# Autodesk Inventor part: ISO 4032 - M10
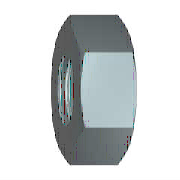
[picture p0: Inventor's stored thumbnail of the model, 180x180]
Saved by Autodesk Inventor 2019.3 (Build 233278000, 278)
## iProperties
Created: 2018-01
Part Number: ISO 4032 - M10
Material: Nerezová ocel 440C
Description: Šestihranné matice, styl 1 – s jemným metrickým závitem. Výrobní řada A a B
Document SubType Name: Modeling
Standard: ISO 4032
Designer: B-hon
Standards Organization: CSN
Language: cs-CZ
Size Designation: M10
Categories: <MemberInstance><Categories><Category DisplayName="Spojovací materiál" InternalName="e4da775c-781d-43d5-af7c-5136215cf5a6" Mnemonic="FSTN"><Category DisplayName
Density: 7.75 g/cm^3
Appearance: Pololeštěná
IsCustomPart: 0
Author: B-hon
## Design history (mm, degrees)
sketch "Náčrt1"
  geometry: L1 (-9.238, 0)-(-4.619, 8); L2 (-4.619, 8)-(4.619, 8); L3 (4.619, 8)-(9.238, 0); L4 (9.238, 0)-(4.619, -8); L5 (4.619, -8)-(-4.619, -8); L6 (-4.619, -8)-(-9.238, 0); 2 further points
  constraints: 12 end point, 1 coincident, 1 horizontal, 11 other
  dimensions: "d0" = 18.47521 distance of L3.end L1.start (= 1.1547 x SW)
extrude "Těleso" new body sketch "Náčrt1" distance "d1" = 8.4 (= KOH); taper "d2" = 0 deg
sketch "Náčrt2"
  geometry: L1 (0, 4.619)-(0, 9.238) reference; L2 (0, 9.238)-(8.4, 9.238) reference; L3 (8.4, 4.619)-(8.4, 9.238) reference; L4 (-1.68, 0)-(10.08, 0) reference; L5 (0.715, 9.238)-(0, 8); L6 (7.685, 9.238)-(8.4, 8)
  constraints: 4 end point, 4 point on line
  dimensions: "d3" = 30 deg angle of L1 L5 (= ANG1); "d4" = 30 deg angle of L3 L6 (= ANG2); "d5" = 16 diameter of L5.end L4 (= SW0); "d6" = 16 diameter of L6.end L4 (= SW01)
revolve "Zkosení1" sketch "Náčrt2" stored, may be unused: angle "d7" = 90 deg
sketch "Náčrt3"
  geometry: A1 r 8 centre (0, 0) between (-4, -6.928) and (4, -6.928) reference; 1 further point
  constraints: 1 coincident
hole "Závit" sketch "Náčrt3" at (0, 0) diameter "d25" = 8.376; stored, may be unused: countersink angle "d29" = 82 deg, drill point angle "d31" = 118 deg; dims "d26" = 6, "d27" = 4, "d28" = 2, "d30" = 8
workaxis "Work Axis1"
workplane "Work Plane1"
body "Solid1"
chamfer "Zkosení2" distance "d8" = 0.8119 (= -0.5 x GD1 + 0.5 x NND); stored, may be unused: angle "d9" = 30 deg, second distance "d40" = 0.8119 (= -0.5 x GD1 + 0.5 x NND)
chamfer "Zkosení3" distance "d10" = 0.8119 (= -0.5 x GD1 + 0.5 x NND); stored, may be unused: angle "d11" = 30 deg, second distance "d41" = 0.8119 (= -0.5 x GD1 + 0.5 x NND)
other parameters: "ANG1" = 30 deg [user parameter; used in 1 equation term], "ANG2" = 30 deg [user parameter; used in 1 equation term], "KOH" = 8.4 [user parameter; used in 1 equation term], "SW" = 16 [user parameter; used in 2 equation terms], "SW0" = 16 [user parameter; used in 2 equation terms], "SW01" = 16 (= SW0) [user parameter; used in 1 equation term], "GD1" = 8.3762 (computed from THREADDIA, PTC, TOA) [user parameter; used in 4 equation terms], "d13" = 0, "d14" = 0, "d39" = 0, "d42" = 0, "GUL" = 0.8119 (= 0.541266 x PTC) [user parameter], "TPU" = 6.66667 (computed from PTC) [user parameter], "TOA" = 30 deg [user parameter; used in 1 equation term], "PTC" = 1.5 [user parameter; used in 4 equation terms], "E0" = 18.48 (= 1.155 x SW) [user parameter], "GAL" = 0.8119 (= 0.541266 x PTC) [user parameter]
